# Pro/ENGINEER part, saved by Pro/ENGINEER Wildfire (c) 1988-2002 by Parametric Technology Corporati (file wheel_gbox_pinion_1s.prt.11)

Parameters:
  PTNUM = "A_1C_2MYK20025"
  PTNAME = "SPUR_GEARS-MODULE_2-0"
  MFG = "Stock_Drive_Products"
  WEIGHT = "*"
  MATERIAL = "STEEL"

Other parameters: TEETH, MODULE, OUTSIDE_DIA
